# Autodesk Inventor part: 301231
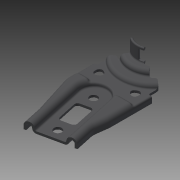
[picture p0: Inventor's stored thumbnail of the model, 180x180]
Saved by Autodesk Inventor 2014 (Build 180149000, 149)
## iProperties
Created: 2007-11
Part Number: 301231
Document SubType Name: Modeling
Designer: TH
Density: 7.85 g/cm^3
Mass: 265.869 g
Surface Area: 247.179 cm^2
Volume: 33.8686 cm^3
Material: Steel
Description: RIGHT SIDE SPRING BACKET
Appearance: Gray
Component Category: Back Component
Author: TH
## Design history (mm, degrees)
sketch "Sketch1"
  geometry: L1 (37.178, -114.919)-(42.947, -141.572); L2 (37.178, -114.919)-(39.809, -94.549); L3 (39.809, -94.549)-(39.809, -27.808); L4 (-17.211, -154.594)-(-22.902, -128.301); L5 (-22.902, -128.301)-(-39.713, -74.672); L6 (-39.713, -74.672)-(-39.713, -29.063); L7 (-17.211, -154.594)-(42.947, -141.572); L8 (33.212, -22.272)-(39.809, -27.808); L9 (0, 37.553)-(0, -186.618) reference; L10 (0.081, 5.528)-(0, 5.458); L11 (-32.561, -22.846)-(-39.713, -29.063); A1 r 43.25 centre (0.081, 5.528) between (-32.561, -22.846) and (33.212, -22.272); 1 further point
  constraints: 20 end point, 2 parallel, 2 point on circle, 1 centre point, 1 perpendicular, 1 point on line, 1 vertical
  dimensions: "d1" = 39.72897 horizontal distance of L10.start L3.end; "d2" = 50 deg angle of L8 L9; "d3" = 99 deg angle of L8 L11; "d4" = 43.25002 radius of A1; "d5" = 79.52221 distance between parallel lines of L6 L3; "d6" = 39.71273 horizontal distance of point (0, 0) L6.end; "d7" = 74.67218 vertical distance of L5.end point (0, 0); "d8" = 128.30072 vertical distance of point (0, 0) L4.end; "d9" = 154.59384 vertical distance of point (0, 0) L4.start; "d10" = 27.8081 vertical distance of point (0, 0) L3.end; "d11" = 114.91898 vertical distance of point (0, 0) L1.start; "d12" = 141.5725 vertical distance of point (0, 0) L1.end; "d13" = 22.27211 vertical distance of point (0, 0) L8.start; "d14" = 22.8461 vertical distance of point (0, 0) L11.start; "d15" = 94.54884 vertical distance of point (0, 0) L2.end; "d16" = 22.90243 distance from line of L9 L4.end; "d17" = 37.17797 distance from line of L1.start L9
extrude "Extrusion1" new body sketch "Sketch1" distance "d18" = 14.2; taper "d19" = 0 deg
sketch "Sketch2"
  geometry: L1 (39.809, -27.808)-(39.809, -94.549) reference; L2 (33.212, -22.272)-(39.809, -27.808) reference; L3 (-39.713, -29.063)-(-32.561, -22.846) reference; L4 (-39.713, -74.672)-(-39.713, -29.063) reference; L5 (39.809, -60.635)-(-39.713, -60.635); A1 r 43.25 centre (0.081, 5.528) between (-32.561, -22.846) and (33.212, -22.272) reference; 1 further point
  constraints: 2 end point, 2 point on line, 1 perpendicular
  dimensions: "d20" = 60.63512 distance from line of L5 point (0, 0)
sketch "Sketch3"
  geometry: L1 (42.947, -141.572)-(-17.211, -154.594) reference; L2 (-3.225, -73.418)-(-20.84, -77.231); L3 (-20.84, -77.231)-(-4.681, -151.882); L4 (-3.225, -73.418)-(14.389, -69.605); L5 (14.389, -69.605)-(30.548, -144.256); A1 r 18.022 centre (-3.225, -73.418) between (-20.84, -77.231) and (14.389, -69.605); 1 further point
  constraints: 8 end point, 3 perpendicular, 2 point on circle, 2 point on line, 2 tangent, 1 centre point
  dimensions: "d23" = 36.04481 diameter of A1; "d24" = 73.41791 vertical distance of point (0, 0) L2.start; "d25" = 3.22521 horizontal distance of point (0, 0) L2.start
extrude "Extrusion3" cut sketch "Sketch3" distance "d26" = 8.2; taper "d27" = 0 deg
fillet "Fillet2" dims "d29" = 20
fillet "Fillet3" dims "d30" = 6.33
extrude "Extrusion4" cut sketch "Sketch2" distance "d31" = 3.15; taper "d32" = 0 deg
fillet "Fillet4" dims "d33" = 3
fillet "Fillet5" dims "d34" = 2
fillet "Fillet6" dims "d35" = 2
fillet "Fillet7" dims "d37" = 2
shell "Shell1" dims "d36" = 3
fillet "Fillet8" dims "d38" = 1
sketch "Sketch4"
  geometry: L1 (-37.549, -59.276)-(-37.549, -27.182) reference; L2 (37.646, -25.992)-(37.646, -59.276) reference; L3 (33.212, -22.272)-(37.646, -25.992) reference; L4 (-37.549, -27.182)-(-32.561, -22.846) reference; L5 (39.809, -93.262)-(39.809, -27.808) reference; L6 (-39.713, -29.063)-(-39.713, -71.611) reference; L7 (39.809, -37)-(34.809, -37); L8 (34.809, -37)-(34.809, -23.613); L9 (-39.713, -37)-(-34.713, -37); L10 (-34.713, -37)-(-34.713, -24.717); L11 (34.809, -23.613)-(39.809, -27.808); L12 (39.809, -37)-(39.809, -27.808); L13 (-39.713, -37)-(-39.713, -29.063); L14 (-39.713, -29.063)-(-34.713, -24.717); 1 further point
  constraints: 16 end point, 4 collinear, 4 perpendicular, 4 point on line
  dimensions: "d39" = 37 distance from line of L7 point (0, 0); "d40" = 37 distance from line of point (0, 0) L9 (= d39); "d41" = 5 distance of L7.start L7.end; "d42" = 5 distance of L9.start L9.end
extrude "Extrusion5" cut sketch "Sketch4" stored distance "d43" = 3.15; taper "d44" = 0 deg
sketch "Sketch5"
  geometry: L1 (-39.809, -93.262)-(-39.809, -37) reference; L2 (-37.62, -111.497)-(-39.645, -95.825) reference; L3 (-42.947, -141.572)-(-37.908, -118.291) reference; L4 (39.713, -37)-(36.713, -37) reference; L5 (36.713, -37)-(36.713, -71.611) reference; L6 (35.934, -76.696)-(20.311, -126.538) reference; L7 (19.779, -128.552)-(14.279, -153.959) reference; L8 (17.211, -154.594)-(14.279, -153.959) reference; L9 (22.711, -129.187)-(17.211, -154.594) reference; L10 (38.797, -77.593)-(23.174, -127.436) reference; L11 (39.713, -37)-(39.713, -71.611) reference; L12 (-42.947, -141.572)-(17.211, -154.594); L13 (39.713, -37)-(-39.809, -37); A1 r 20 centre (-19.809, -93.262) between (-39.809, -93.262) and (-39.645, -95.825) reference; A2 r 20 centre (-57.455, -114.06) between (-37.908, -118.291) and (-37.62, -111.497) reference; A3 r 17 centre (19.713, -71.611) between (35.934, -76.696) and (36.713, -71.611) reference; A4 r 23 centre (42.258, -133.418) between (20.311, -126.538) and (19.779, -128.552) reference; A5 r 20 centre (42.258, -133.418) between (23.174, -127.436) and (22.711, -129.187) reference; A6 r 20 centre (19.713, -71.611) between (38.797, -77.593) and (39.713, -71.611) reference; 1 further point
  constraints: 4 end point, 2 perpendicular
extrude "Extrusion6" cut sketch "Sketch5" distance "d45" = 3; taper "d46" = 0 deg
fillet "Fillet9" dims "d47" = 1.68
fillet "Fillet10" dims "d48" = 1.95
sketch "Sketch6"
  geometry: L1 (37.646, -37)-(36.489, -37) reference; L2 (33.212, -22.272)-(34.809, -23.613) reference; L3 (33.212, -22.272)-(34.809, -23.613); L4 (34.809, -23.613)-(34.809, -25.016); L5 (-34.713, -24.717)-(-32.561, -22.846) reference; L6 (-34.713, -24.717)-(-34.713, -24.943); A1 r 43.25 centre (0.081, 5.528) between (-32.561, -22.846) and (33.212, -22.272) reference; A2 r 46.25 centre (0.081, 5.528) between (-34.713, -24.943) and (34.809, -25.016); 1 further point
  constraints: 6 end point, 2 point on circle, 1 centre point, 1 collinear, 1 parallel, 1 perpendicular
  dimensions: "d49" = 3 radial gap between concentric circles of A2 A1
extrude "Extrusion7" join sketch "Sketch6" distance "d50" = 5.55; taper "d51" = 0 deg
sketch "Sketch7"
  geometry: L1 (-34.713, -24.943)-(-34.713, -24.717) reference; L2 (34.809, -23.613)-(34.809, -25.016) reference; L3 (33.212, -22.272)-(25.552, -15.844); L4 (34.809, -23.613)-(33.212, -22.272); L5 (-25.014, -16.286)-(-34.713, -24.717); L6 (-34.713, -24.717)-(-32.561, -22.846) reference; A1 r 43.25 centre (0.081, 5.528) between (-32.561, -22.846) and (33.212, -22.272) reference; A2 r 46.25 centre (0.081, 5.528) between (-34.713, -24.943) and (34.809, -25.016) reference; A3 r 33.25 centre (0.081, 5.528) between (-25.014, -16.286) and (25.552, -15.844); 1 further point
  constraints: 6 end point, 2 collinear, 2 point on circle, 1 centre point
  dimensions: "d52" = 10 radial gap between concentric circles of A3 A1
extrude "Extrusion8" join sketch "Sketch7" distance "d53" = 3; taper "d54" = 0 deg
sketch "Sketch8"
  geometry: L1 (-19.998, -21.096)-(-18.201, -18.694); L2 (19.837, -21.096)-(18.04, -18.694); L3 (0, -186.618)-(0, 37.553) reference; A1 r 33.25 centre (-0.081, 5.528) between (-25.552, -15.844) and (25.014, -16.286) reference; A2 r 30.25 centre (-0.081, 5.528) between (-18.201, -18.694) and (18.04, -18.694); 1 further point
  constraints: 4 end point, 4 point on circle, 2 point on line, 1 centre point
  dimensions: "d55" = 3 radial gap between concentric circles of A2 A1; "d63" = 36.8 deg angle of L3 L1; "d64" = 36.8 deg angle of L3 L2
extrude "Extrusion9" join sketch "Sketch8" distance "d56" = 10.15; taper "d57" = 0 deg
sketch "Sketch9"
  geometry: L1 (-13.967, -13.249)-(-18.04, -18.694); L2 (18.201, -18.694)-(14.128, -13.249); L3 (0, 37.553)-(0, -186.618) reference; A1 r 30.25 centre (0.081, 5.528) between (-18.04, -18.694) and (18.201, -18.694) reference; A2 r 23.45 centre (0.081, 5.528) between (-13.967, -13.249) and (14.128, -13.249); 1 further point
  constraints: 4 end point, 2 point on circle, 2 point on line, 1 centre point
  dimensions: "d58" = 6.8 radial gap between concentric circles of A1 A2
extrude "Extrusion10" join sketch "Sketch9" distance "d61" = 3; taper "d62" = 0 deg
sketch "Sketch11"
  geometry: L1 (18.04, -18.694)-(12.17, -10.847); L2 (-8.408, -16.393)-(-7.342, -13.589); A1 r 23.45 centre (-0.081, 5.528) between (-14.128, -13.249) and (13.967, -13.249) reference; A2 r 30.25 centre (-0.081, 5.528) between (-18.201, -18.694) and (18.04, -18.694) reference; A3 r 20.45 centre (-0.081, 5.528) between (-7.342, -13.589) and (12.17, -10.847); 1 further point
  constraints: 4 end point, 3 point on circle, 2 point on line, 1 centre point, 1 coincident
  dimensions: "d65" = 3 radial gap between concentric circles of A3 A1; "d66" = 57.6 deg angle of L2 L1
extrude "Extrusion11" join sketch "Sketch11" distance "d67" = 21.25; taper "d68" = 0 deg
fillet "Fillet11" dims "d69" = 5, "d70" = 2
sketch "Sketch12"
  geometry: L1 (-21.035, -22.697)-(-19.837, -21.096) reference; L2 (-25.014, -16.286)-(-31.051, -21.534) reference; L3 (25.552, -15.844)-(31.68, -20.987) reference; L4 (19.998, -21.096)-(21.196, -22.697) reference; A1 r 33.25 centre (0.081, 5.528) between (-25.014, -16.286) and (-19.837, -21.096) reference; A2 r 33.25 centre (0.081, 5.528) between (19.998, -21.096) and (25.552, -15.844) reference; A3 r 35.25 centre (0.081, 5.528) between (-21.035, -22.697) and (21.196, -22.697) reference; A4 r 35.25 centre (0.081, 5.528) between (21.196, -22.697) and (27.084, -17.13); A5 r 35.25 centre (0.081, 5.528) between (-26.523, -17.598) and (-21.035, -22.697); 1 further point
  constraints: 4 point on circle, 2 centre point, 2 end point, 2 point on line, 1 coincident
extrude "Extrusion12" cut sketch "Sketch12" stored distance "d71" = 21.25; taper "d72" = 0 deg
sketch "Sketch13"
  geometry: L1 (-16.842, -17.092)-(-15.165, -14.85) reference; L2 (14.128, -13.249)-(17.003, -17.092) reference; L3 (8.408, -16.393)-(9.118, -18.263) reference; A1 r 23.45 centre (0.081, 5.528) between (8.408, -16.393) and (14.128, -13.249) reference; A2 r 25.45 centre (0.081, 5.528) between (9.118, -18.263) and (15.326, -14.85); 1 further point
  constraints: 3 point on circle, 2 point on line, 1 centre point, 1 coincident, 1 end point
extrude "Extrusion13" cut sketch "Sketch13" stored distance "d73" = 21.25; taper "d74" = 0 deg
fillet "Fillet14" dims "d77" = 1.375
fillet "Fillet12" dims "d75" = 3
fillet "Fillet15" dims "d78" = 2
sketch "Sketch15"
  geometry: L1 (70.522, 23.305)-(70.522, 30.455) reference; L2 (58.884, 8.799)-(56.934, 9.925); L3 (56.934, 17.286)-(58.884, 18.412); L4 (65.259, 14.731)-(65.259, 12.479); L5 (6.359, 12.479)-(6.359, 14.731); L6 (12.734, 18.412)-(14.684, 17.286); L7 (14.684, 9.925)-(12.734, 8.799); A1 r 4.25 centre (61.009, 12.479) between (58.884, 8.799) and (65.259, 12.479) reference; A2 r 4.25 centre (59.059, 13.605) between (56.934, 17.286) and (56.934, 9.925) reference; A3 r 4.25 centre (61.009, 14.731) between (65.259, 14.731) and (58.884, 18.412) reference; A4 r 4.25 centre (10.609, 12.479) between (6.359, 12.479) and (12.734, 8.799) reference; A5 r 4.25 centre (12.559, 13.605) between (14.684, 9.925) and (14.684, 17.286) reference; A6 r 4.25 centre (10.609, 14.731) between (12.734, 18.412) and (6.359, 14.731) reference; 1 further point
  constraints: 12 end point, 12 point on circle, 11 tangent, 6 centre point, 4 parallel, 24 other
extrude "Extrusion14" cut sketch "Sketch15" stored distance "d79" = 10; taper "d80" = 0 deg
sketch "Sketch16"
  geometry: L1 (28.594, -144.679)-(-2.728, -151.459) reference; L2 (12.436, -70.028)-(-18.886, -76.808); L3 (-3.225, -73.418)-(10.208, -135.481); 3 further points
  constraints: 4 end point, 2 coincident, 1 midpoint, 1 parallel, 1 perpendicular
  dimensions: "d81" = 63.5 distance of L3.start L3.end
hole "Hole1" sketch "Sketch16" at (10.208, -135.481), (-3.225, -73.418) diameter "d82" = 10.5; stored, may be unused: countersink angle "d86" = 90 deg, drill point angle "d88" = 118 deg; dims "d83" = 6, "d84" = 4, "d85" = 2, "d87" = 8
sketch "Sketch17"
  geometry: L1 (12.436, -70.028)-(28.594, -144.679) reference; L2 (-2.728, -151.459)-(-18.886, -76.808) reference; L3 (28.594, -144.679)-(-2.728, -151.459) reference; L4 (15.985, -114.79)-(10.591, -89.867); L5 (5.835, -86.804)-(-5.939, -89.353); L6 (-9.002, -94.108)-(-3.608, -119.031); L7 (12.922, -119.546)-(1.148, -122.094); C1 r 5.25 at (-3.225, -73.418) reference; C2 r 5.25 at (10.208, -135.481) reference; A1 r 4 centre (12.076, -115.636) between (12.922, -119.546) and (15.985, -114.79); A2 r 4 centre (0.302, -118.185) between (-3.608, -119.031) and (1.148, -122.094); A3 r 4 centre (-5.093, -93.262) between (-5.939, -89.353) and (-9.002, -94.108); A4 r 4 centre (6.681, -90.714) between (10.591, -89.867) and (5.835, -86.804); 1 further point
  constraints: 8 end point, 8 point on circle, 8 tangent, 4 centre point, 3 equal radius, 3 perpendicular, 1 parallel
  dimensions: "d89" = 6 distance between parallel lines of L1 L4; "d90" = 6 distance between parallel lines of L2 L6; "d91" = 15 distance from line of C2.centre L7; "d92" = 15 distance from line of L5 C1.centre (= d91); "d93" = 4 radius of A1
extrude "Extrusion15" cut sketch "Sketch17" stored distance "d94" = 10; taper "d95" = 0 deg
sketch "Sketch18"
  geometry: L1 (14.875, 0)-(0, 0) reference; L2 (14.875, -3)-(1.875, -3); L3 (1.875, -3)-(1.875, 0); L4 (1.875, 0)-(14.875, 0); L5 (14.875, 0)-(14.875, -3); L6 (14.875, 0)-(1.875, 0); L7 (1.875, 0)-(1.875, 1); L8 (1.875, 1)-(14.875, 1); L9 (14.875, 1)-(14.875, 0); 1 further point
  constraints: 16 end point, 4 parallel, 2 horizontal, 2 perpendicular, 1 point on line
  dimensions: "d96" = 13 distance of L3.end L4.end; "d99" = 1 distance of L3.end L7.end
extrude "Extrusion16" cut sketch "Sketch18" distance "d97" = 6; taper "d98" = 0 deg
fillet "Fillet16" dims "d100" = 0.5
fillet "Fillet17" dims "d101" = 0.5
fillet "Fillet18" dims "d102" = 0.5
body "Solid1"
node "Projected Loop1"
other parameters: "d0" = 99 deg
